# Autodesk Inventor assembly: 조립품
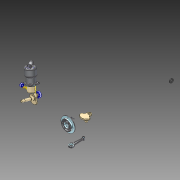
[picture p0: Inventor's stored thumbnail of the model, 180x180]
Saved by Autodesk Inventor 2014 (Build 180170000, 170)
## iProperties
Created: 2015-06
Part Number: 조립품
Document SubType Name: Assembly
Designer: user
Author: user
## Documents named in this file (15)
- C:\Users\user\Desktop\450606v1011\조립품.iam
- C:\Users\user\Desktop\450606v1011\본체.ipt
- C:\Users\user\Desktop\450606v1011\M4x0.7.ipt
- C:\Users\user\Desktop\450606v1011\M5x0.8.ipt
- C:\Users\user\Desktop\450606v1011\메인 크랭크 축-구동부.ipt
- C:\Users\user\Desktop\450606v1011\메인커버.ipt
- C:\Users\user\Desktop\450606v1011\베어링 6204.ipt
- C:\Users\user\Desktop\450606v1011\베어링 NA 4902.ipt
- C:\Users\user\Desktop\450606v1011\실린더.ipt
- C:\Users\user\Desktop\450606v1011\실린더헤드.ipt
- C:\Users\user\Desktop\450606v1011\오일실.ipt
- C:\Users\user\Desktop\450606v1011\커넥팅 로드.ipt
- C:\Users\user\Desktop\450606v1011\크랭크 서브축.ipt
- C:\Users\user\Desktop\450606v1011\피스톤 핀.ipt
- C:\Users\user\Desktop\450606v1011\피스톤.ipt
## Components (4 placed, 4 different names)
1. M4x0.7:1
2. M5x0.8:1
3. 피스톤 핀:1 — Mate:3
4. 피스톤:2 — Insert:4, Mate:3
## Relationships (2: Insert 1, Mate 1)
- Insert:4: 피스톤:2
- Mate:3: 피스톤 핀:1 ↔ 피스톤:2
